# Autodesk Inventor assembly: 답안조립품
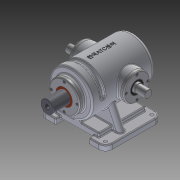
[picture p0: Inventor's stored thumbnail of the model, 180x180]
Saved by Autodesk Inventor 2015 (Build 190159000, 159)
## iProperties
Created: 2015-10
Part Number: 답안조립품
Document SubType Name: Assembly
Designer: youjin22
Mass: 9437.34 g
Surface Area: 4327.34 cm^2
Volume: 2315.26 cm^3
Density: 4.07615 g/cm^3
Author: youjin22
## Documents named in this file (13)
- C:\Users\youjin22\Desktop\351019V1015\답안조립품.iam
- C:\Users\youjin22\Desktop\351019V1015\본체.ipt
- C:\Users\youjin22\Desktop\351019V1015\축 커버.ipt
- C:\Users\youjin22\Desktop\351019V1015\M4x0.7.ipt
- C:\Users\youjin22\Desktop\351019V1015\오일실.ipt
- 오일실.ipt
- C:\Users\youjin22\Desktop\351019V1015\베어링 6205.ipt
- 베어링 6205.ipt
- C:\Users\youjin22\Desktop\351019V1015\편심축.ipt
- C:\Users\youjin22\Desktop\351019V1015\슬라이드 커버.ipt
- C:\Users\youjin22\Desktop\351019V1015\부시.ipt
- C:\Users\youjin22\Desktop\351019V1015\가변스프링.ipt
- C:\Users\youjin22\Desktop\351019V1015\슬라이드.ipt
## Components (13 placed, 2 different names)
1. 가변스프링:1 — Mate:23, Mate:24, Mate:25, Mate:26
2. M4x0.7:1 — Insert:1
3. M4x0.7:2
4. M4x0.7:3
5. M4x0.7:4
6. M4x0.7:5 — Insert:2
7. M4x0.7:6
8. M4x0.7:7
9. M4x0.7:8
10. M4x0.7:9 — Insert:3
11. M4x0.7:10
12. M4x0.7:11
13. M4x0.7:12
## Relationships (7: Mate 4, Insert 3)
- Insert:1: M4x0.7:1
- Insert:2: M4x0.7:5
- Insert:3: M4x0.7:9
- Mate:23: 가변스프링:1
- Mate:24: 가변스프링:1
- Mate:25: 가변스프링:1
- Mate:26: 가변스프링:1
